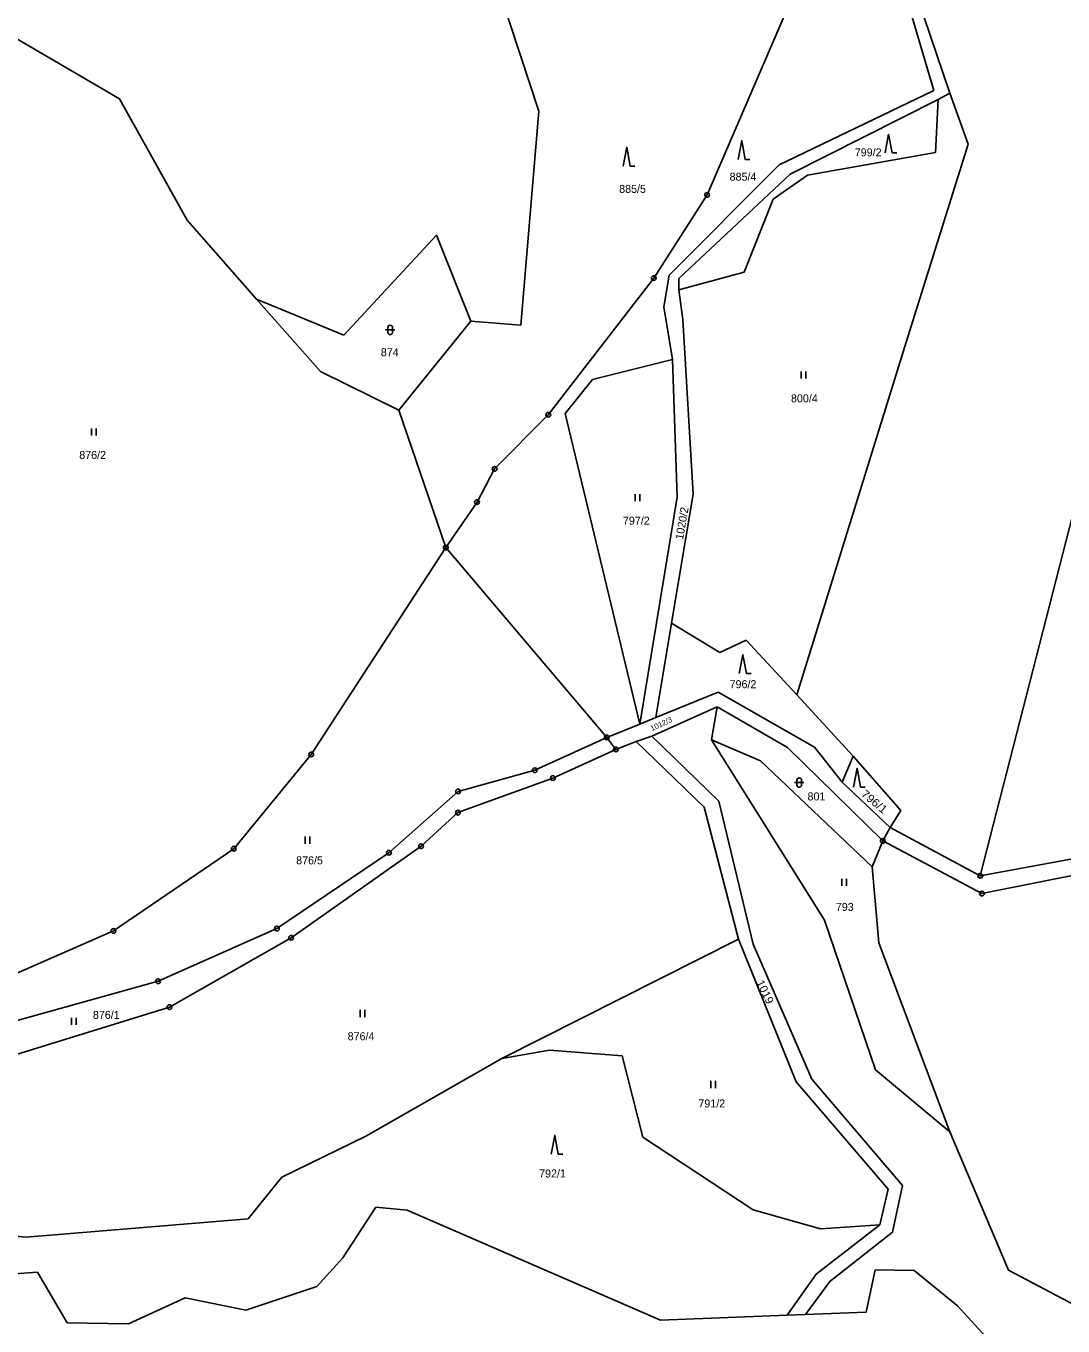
# Model space of a CAD drawing. Extents: x -754970 to -752637, y -970569 to -968179.
# Drawn here: x -753399.6 to -753179.3, y -970118 to -969841.9 of the extents above; entities that cross this region are included whole.
import ezdxf
from ezdxf.enums import TextEntityAlignment as Align

# ---------------------------------------------------------------- set-up
doc = ezdxf.new("R2010")
doc.units = 0
doc.header["$LTSCALE"] = 0.68
for name, color, linetype, lineweight in [('1', 7, 'Continuous', 25), ('3', 7, 'Continuous', 25), ('8', 7, 'Continuous', 25)]:
    doc.layers.add(name, color=color, linetype=linetype, lineweight=lineweight)
doc.layers.add('2', color=7, linetype='Continuous')

msp = doc.modelspace()

# ---------------------------------------------------------------- linework, layer by layer
at = {"layer": '1'}
for p, q in [((-753290.64, -969859.99), (-753299.64, -969832.77)), ((-753254.92, -969877.76), (-753236.47, -969834.94)), ((-753212.9, -969834.82), (-753206.76, -969855.56)), ((-753203.35, -969856.12), (-753210.6, -969834.73)), ((-753405.36, -969842.43), (-753379.74, -969857.37)), ((-753379.74, -969857.37), (-753365.35, -969883.13)), ((-753206.76, -969855.56), (-753239.65, -969871.38)), ((-753237.26, -969873.32), (-753205.85, -969857.49)), ((-753205.85, -969857.49), (-753206.42, -969868.76)), ((-753205.85, -969857.49), (-753203.35, -969856.12)), ((-753203.35, -969856.12), (-753199.48, -969866.94)), ((-753294.47, -969905.42), (-753290.64, -969859.99)), ((-753212.61, -969909.07), (-753199.48, -969866.94)), ((-753206.42, -969868.76), (-753233.62, -969873.54)), ((-753239.65, -969871.38), (-753262.99, -969894.83)), ((-753260.94, -969895.52), (-753237.26, -969873.32)), ((-753233.62, -969873.54), (-753240.91, -969878.67)), ((-753266.27, -969895.43), (-753254.92, -969877.76)), ((-753240.91, -969878.67), (-753247.05, -969894.15)), ((-753350.63, -969899.88), (-753365.35, -969883.13)), ((-753332.08, -969907.53), (-753312.4, -969886.28)), ((-753312.4, -969886.28), (-753305.1, -969904.6)), ((-753288.65, -969924.45), (-753266.27, -969895.43)), ((-753262.99, -969894.83), (-753264.08, -969901.56)), ((-753260.94, -969897.91), (-753247.05, -969894.15)), ((-753260.94, -969897.91), (-753260.94, -969895.52)), ((-753260.1, -969904.25), (-753260.94, -969897.91)), ((-753350.63, -969899.88), (-753332.08, -969907.53)), ((-753337.02, -969915.29), (-753350.63, -969899.88)), ((-753264.08, -969901.56), (-753262.3, -969912.69)), ((-753260.1, -969904.25), (-753257.91, -969941.31)), ((-753320.39, -969923.5), (-753305.1, -969904.6)), ((-753305.1, -969904.6), (-753294.47, -969905.42)), ((-753212.61, -969909.07), (-753235.88, -969983.97)), ((-753279.28, -969916.97), (-753262.3, -969912.69)), ((-753262.3, -969912.69), (-753261.31, -969941.97)), ((-753168.42, -969911.09), (-753196.89, -970022.39)), ((-753337.02, -969915.29), (-753320.39, -969923.5)), ((-753285.09, -969924.21), (-753279.28, -969916.97)), ((-753310.42, -969952.68), (-753320.39, -969923.5)), ((-753300.05, -969935.97), (-753288.65, -969924.45)), ((-753269.2, -969990.21), (-753285.09, -969924.21)), ((-753303.8, -969943), (-753300.05, -969935.97)), ((-753310.42, -969952.68), (-753303.8, -969943)), ((-753261.31, -969941.97), (-753269.2, -969990.21)), ((-753262.52, -969968.73), (-753257.91, -969941.31)), ((-753339, -969996.62), (-753310.42, -969952.68)), ((-753276.25, -969993.01), (-753310.42, -969952.68)), ((-753265.81, -969988.8), (-753262.52, -969968.73)), ((-753262.52, -969968.73), (-753252.21, -969974.98)), ((-753246.62, -969972.35), (-753252.21, -969974.98)), ((-753235.88, -969983.97), (-753246.62, -969972.35)), ((-753265.81, -969988.8), (-753252.54, -969983.42)), ((-753252.54, -969983.42), (-753232.08, -969995.06)), ((-753235.88, -969983.97), (-753223.93, -969997.01)), ((-753253.96, -969993.5), (-753252.76, -969986.49)), ((-753252.76, -969986.49), (-753237.85, -969995.15)), ((-753269.2, -969990.21), (-753265.81, -969988.8)), ((-753276.25, -969993.01), (-753269.2, -969990.21)), ((-753266.68, -969992.74), (-753269.97, -969993.84)), ((-753291.53, -969999.97), (-753276.25, -969993.01)), ((-753287.68, -970001.63), (-753274.32, -969995.56)), ((-753274.32, -969995.56), (-753276.25, -969993.01)), ((-753269.97, -969993.84), (-753274.32, -969995.56)), ((-753269.97, -969993.84), (-753255.58, -970007.81)), ((-753243.55, -969998), (-753253.96, -969993.5)), ((-753253.96, -969993.5), (-753230.02, -970031.81)), ((-753237.85, -969995.15), (-753217.6, -970015.01)), ((-753226.23, -970002.49), (-753232.08, -969995.06)), ((-753355.47, -970016.64), (-753339, -969996.62)), ((-753219.88, -970020.47), (-753243.55, -969998)), ((-753226.23, -970002.49), (-753223.93, -969997.01)), ((-753223.93, -969997.01), (-753213.74, -970008.52)), ((-753307.83, -970004.49), (-753291.53, -969999.97)), ((-753307.85, -970008.99), (-753287.68, -970001.63)), ((-753216.05, -970012.13), (-753226.23, -970002.49)), ((-753322.52, -970017.5), (-753307.83, -970004.49)), ((-753252.42, -970006.52), (-753245.14, -970036.91)), ((-753315.69, -970016.13), (-753307.85, -970008.99)), ((-753248.29, -970035.89), (-753255.58, -970007.81)), ((-753216.05, -970012.13), (-753213.74, -970008.52)), ((-753196.89, -970022.39), (-753119.8, -970008.12)), ((-753216.05, -970012.13), (-753217.6, -970015.01)), ((-753216.05, -970012.13), (-753196.89, -970022.39)), ((-753196.54, -970026.18), (-753122.83, -970011.36)), ((-753381.02, -970034.1), (-753355.47, -970016.64)), ((-753346.3, -970033.6), (-753322.52, -970017.5)), ((-753343.28, -970035.56), (-753315.69, -970016.13)), ((-753217.6, -970015.01), (-753219.88, -970020.47)), ((-753217.6, -970015.01), (-753196.54, -970026.18)), ((-753218.45, -970036.65), (-753219.88, -970020.47)), ((-753401.67, -970043.19), (-753381.02, -970034.1)), ((-753371.54, -970044.79), (-753346.3, -970033.6)), ((-753230.02, -970031.81), (-753219.16, -970063.62)), ((-753369.12, -970050.31), (-753343.28, -970035.56)), ((-753248.29, -970035.89), (-753298.56, -970061.21)), ((-753236.03, -970066.16), (-753248.29, -970035.89)), ((-753245.14, -970036.91), (-753232.66, -970065.59)), ((-753203.36, -970076.77), (-753218.45, -970036.65)), ((-753416.08, -970057.2), (-753371.54, -970044.79)), ((-753417.57, -970065.25), (-753369.12, -970050.31)), ((-753327.4, -970077.75), (-753298.56, -970061.21)), ((-753298.56, -970061.21), (-753288.37, -970059.48)), ((-753288.37, -970059.48), (-753272.98, -970060.63)), ((-753272.98, -970060.63), (-753268.56, -970077.94)), ((-753219.16, -970063.62), (-753203.36, -970076.77)), ((-753216.47, -970088.99), (-753236.03, -970066.16)), ((-753232.66, -970065.59), (-753213.43, -970088.2)), ((-753327.4, -970077.75), (-753345.29, -970086.41)), ((-753268.56, -970077.94), (-753245.14, -970093.38)), ((-753203.36, -970076.77), (-753190.89, -970106.2)), ((-753352.4, -970095.26), (-753345.29, -970086.41)), ((-753213.43, -970088.2), (-753215.57, -970098.1)), ((-753325.31, -970092.78), (-753332.28, -970103.56)), ((-753318.65, -970093.47), (-753325.31, -970092.78)), ((-753264.84, -970116.82), (-753318.65, -970093.47)), ((-753245.14, -970093.38), (-753230.86, -970097.43)), ((-753423.76, -970096.89), (-753399.56, -970099.19)), ((-753399.56, -970099.19), (-753352.4, -970095.26)), ((-753230.86, -970097.43), (-753218.27, -970096.53)), ((-753215.57, -970098.1), (-753228.85, -970108.62)), ((-753332.28, -970103.56), (-753337.79, -970109.65)), ((-753397.18, -970106.62), (-753411.9, -970107.67)), ((-753390.88, -970117.35), (-753397.18, -970106.62)), ((-753237.93, -970115.75), (-753231.77, -970107.04)), ((-753234.04, -970115.59), (-753228.85, -970108.62)), ((-753219.26, -970106.13), (-753221.17, -970115.08)), ((-753210.93, -970106.27), (-753219.26, -970106.13)), ((-753201.71, -970113.75), (-753210.93, -970106.27)), ((-753190.89, -970106.2), (-753150.67, -970127.48)), ((-753337.79, -970109.65), (-753352.9, -970114.66)), ((-753365.79, -970112.03), (-753377.84, -970117.57)), ((-753352.9, -970114.66), (-753365.79, -970112.03)), ((-753176.49, -970141.4), (-753201.71, -970113.75)), ((-753264.84, -970116.82), (-753237.93, -970115.75)), ((-753237.93, -970115.75), (-753234.04, -970115.59)), ((-753234.04, -970115.59), (-753221.17, -970115.08)), ((-753377.84, -970117.57), (-753390.88, -970117.35))]:
    msp.add_line(p, q, dxfattribs=at)
for points in [[(-753252.76, -969986.49), (-753266.68, -969992.74), (-753252.42, -970006.52)], [(-753231.77, -970107.04), (-753218.27, -970096.53), (-753216.47, -970088.99)]]:
    msp.add_lwpolyline(points, dxfattribs=at)
at = {"layer": '3'}
for p, q in [((-753246.83, -969870.22), (-753245.834, -969870.22)), ((-753215.63, -969868.85), (-753214.634, -969868.85)), ((-753271.24, -969871.64), (-753270.244, -969871.64)), ((-753323.231, -969906.431), (-753321.229, -969906.431)), ((-753322.731, -969905.931), (-753322.731, -969906.932)), ((-753321.729, -969906.932), (-753321.729, -969905.931)), ((-753234.951, -969916.76), (-753234.951, -969915.26)), ((-753233.95, -969916.76), (-753233.95, -969915.26)), ((-753385.661, -969928.89), (-753385.661, -969927.39)), ((-753384.66, -969928.89), (-753384.66, -969927.39)), ((-753270.191, -969942.85), (-753270.191, -969941.35)), ((-753269.19, -969942.85), (-753269.19, -969941.35)), ((-753246.58, -969979.45), (-753245.584, -969979.45)), ((-753236.351, -970002.601), (-753234.349, -970002.601)), ((-753235.851, -970002.101), (-753235.851, -970003.102)), ((-753234.849, -970003.102), (-753234.849, -970002.101)), ((-753222.32, -970003.56), (-753221.324, -970003.56)), ((-753340.301, -970015.58), (-753340.301, -970014.08)), ((-753339.3, -970015.58), (-753339.3, -970014.08)), ((-753226.291, -970024.55), (-753226.291, -970023.05)), ((-753225.29, -970024.55), (-753225.29, -970023.05)), ((-753389.961, -970054.09), (-753389.961, -970052.59)), ((-753388.96, -970054.09), (-753388.96, -970052.59)), ((-753328.621, -970052.41), (-753328.621, -970050.91)), ((-753327.62, -970052.41), (-753327.62, -970050.91)), ((-753254.161, -970067.49), (-753254.161, -970065.99)), ((-753253.16, -970067.49), (-753253.16, -970065.99)), ((-753286.54, -970081.55), (-753285.544, -970081.55))]:
    msp.add_line(p, q, dxfattribs=at)
for points in [[(-753215.63, -969868.85), (-753216.38, -969864.85), (-753217.13, -969868.85)], [(-753271.24, -969871.64), (-753271.99, -969867.64), (-753272.74, -969871.64)], [(-753246.83, -969870.22), (-753247.58, -969866.22), (-753248.33, -969870.22)], [(-753246.58, -969979.45), (-753247.33, -969975.45), (-753248.08, -969979.45)], [(-753222.32, -970003.56), (-753223.07, -969999.56), (-753223.82, -970003.56)], [(-753286.54, -970081.55), (-753287.29, -970077.55), (-753288.04, -970081.55)]]:
    msp.add_lwpolyline(points, dxfattribs=at)
for centre, start, end in [((-753322.23, -969905.9309), 0, 180), ((-753322.23, -969906.9309), 180, 359.98789), ((-753235.35, -970002.1009), 0, 180), ((-753235.35, -970003.1009), 180, 359.98789)]:
    msp.add_arc(centre, 0.5, start, end, dxfattribs=at)
at = {"layer": '8'}
for centre, radius in [((-753254.92, -969877.7599), 0.5), ((-753254.92, -969877.7599), 0.0303), ((-753266.27, -969895.4299), 0.5), ((-753266.27, -969895.4299), 0.0303), ((-753288.65, -969924.4499), 0.5), ((-753288.65, -969924.4499), 0.0303), ((-753300.05, -969935.9699), 0.5), ((-753300.05, -969935.9699), 0.0303), ((-753303.8, -969942.9999), 0.5), ((-753303.8, -969942.9999), 0.0303), ((-753310.42, -969952.6799), 0.5), ((-753310.42, -969952.6799), 0.0303), ((-753276.25, -969993.0099), 0.5), ((-753276.25, -969993.0099), 0.0303), ((-753274.32, -969995.5599), 0.5), ((-753274.32, -969995.5599), 0.0303), ((-753339, -969996.6199), 0.5), ((-753339, -969996.6199), 0.0303), ((-753291.53, -969999.9699), 0.5), ((-753291.53, -969999.9699), 0.0303), ((-753287.68, -970001.6299), 0.5), ((-753287.68, -970001.6299), 0.0303), ((-753307.83, -970004.4899), 0.5), ((-753307.83, -970004.4899), 0.0303), ((-753307.85, -970008.9899), 0.5), ((-753307.85, -970008.9899), 0.0303), ((-753217.6, -970015.0099), 0.5), ((-753355.47, -970016.6399), 0.5), ((-753355.47, -970016.6399), 0.0303), ((-753322.52, -970017.4999), 0.5), ((-753322.52, -970017.4999), 0.0303), ((-753315.69, -970016.1299), 0.5), ((-753315.69, -970016.1299), 0.0303), ((-753217.6, -970015.0099), 0.0303), ((-753196.89, -970022.3899), 0.5), ((-753196.89, -970022.3899), 0.0303), ((-753196.54, -970026.1799), 0.5), ((-753196.54, -970026.1799), 0.0303), ((-753381.02, -970034.0999), 0.5), ((-753381.02, -970034.0999), 0.0303), ((-753346.3, -970033.5999), 0.5), ((-753346.3, -970033.5999), 0.0303), ((-753343.28, -970035.5599), 0.5), ((-753343.28, -970035.5599), 0.0303), ((-753371.54, -970044.7899), 0.5), ((-753371.54, -970044.7899), 0.0303), ((-753369.12, -970050.3099), 0.5), ((-753369.12, -970050.3099), 0.0303)]:
    msp.add_circle(centre, radius, dxfattribs=at)

# ---------------------------------------------------------------- texts
at = {"layer": '2'}
for s, p in [('799/2', (-753220.71, -969869.565)), ('885/4', (-753247.3, -969874.735)), ('885/5', (-753270.76, -969877.325)), ('874', (-753322.329, -969912.025)), ('800/4', (-753234.26, -969921.815)), ('876/2', (-753385.44, -969933.845)), ('797/2', (-753269.96, -969947.815)), ('796/2', (-753247.3, -969982.545)), ('801', (-753231.699, -970006.395)), ('876/5', (-753339.37, -970019.975)), ('793', (-753225.679, -970029.865)), ('876/1', (-753382.54, -970052.805)), ('876/4', (-753328.43, -970057.345)), ('791/2', (-753253.93, -970071.615)), ('792/1', (-753287.76, -970086.495))]:
    msp.add_text(s, height=1.7, dxfattribs=at).set_placement(p, align=Align.CENTER)
msp.add_text('1020/2', height=1.7, rotation=80, dxfattribs=at).set_placement((-753259.4478, -969947.6681), align=Align.CENTER)
for s, height, rotation, width, p in [('1012/3', 1.14, 25, 1.05, (-753264.4269, -969990.6506)), ('796/1', 1.7, 320, 1.1, (-753219.9444, -970007.2983)), ('1019', 1.7, 296, 1.05, (-753243.3594, -970047.4254))]:
    msp.add_text(s, height=height, rotation=rotation, dxfattribs=dict(at, width=width)).set_placement(p, align=Align.CENTER)

doc.saveas('drawing.dxf')
